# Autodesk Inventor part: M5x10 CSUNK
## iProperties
Created: 2006-12
Part Number: M5x10 CSUNK
Material: Steel, Mild
Description: Hexagon socket countersunk head cap screws
Document SubType Name: Modeling
Standard: DIN 7991
Designer: Andy Moles
Standards Organization: DIN
Language: en-US
Size Designation: M5x16
Categories: <MemberInstance Version="R10.0.0"><Categories><Category DisplayName="Fasteners" InternalName="e4da775c-781d-43d5-af7c-5136215cf5a6" Mnemonic="FSTN"><Category Di
Density: 7.86 g/cm^3
Author: Andy Moles
Revision Number: 1
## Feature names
1. Revolution1
2. Extrusion1
3. Fillet1
4. Chamfer1
